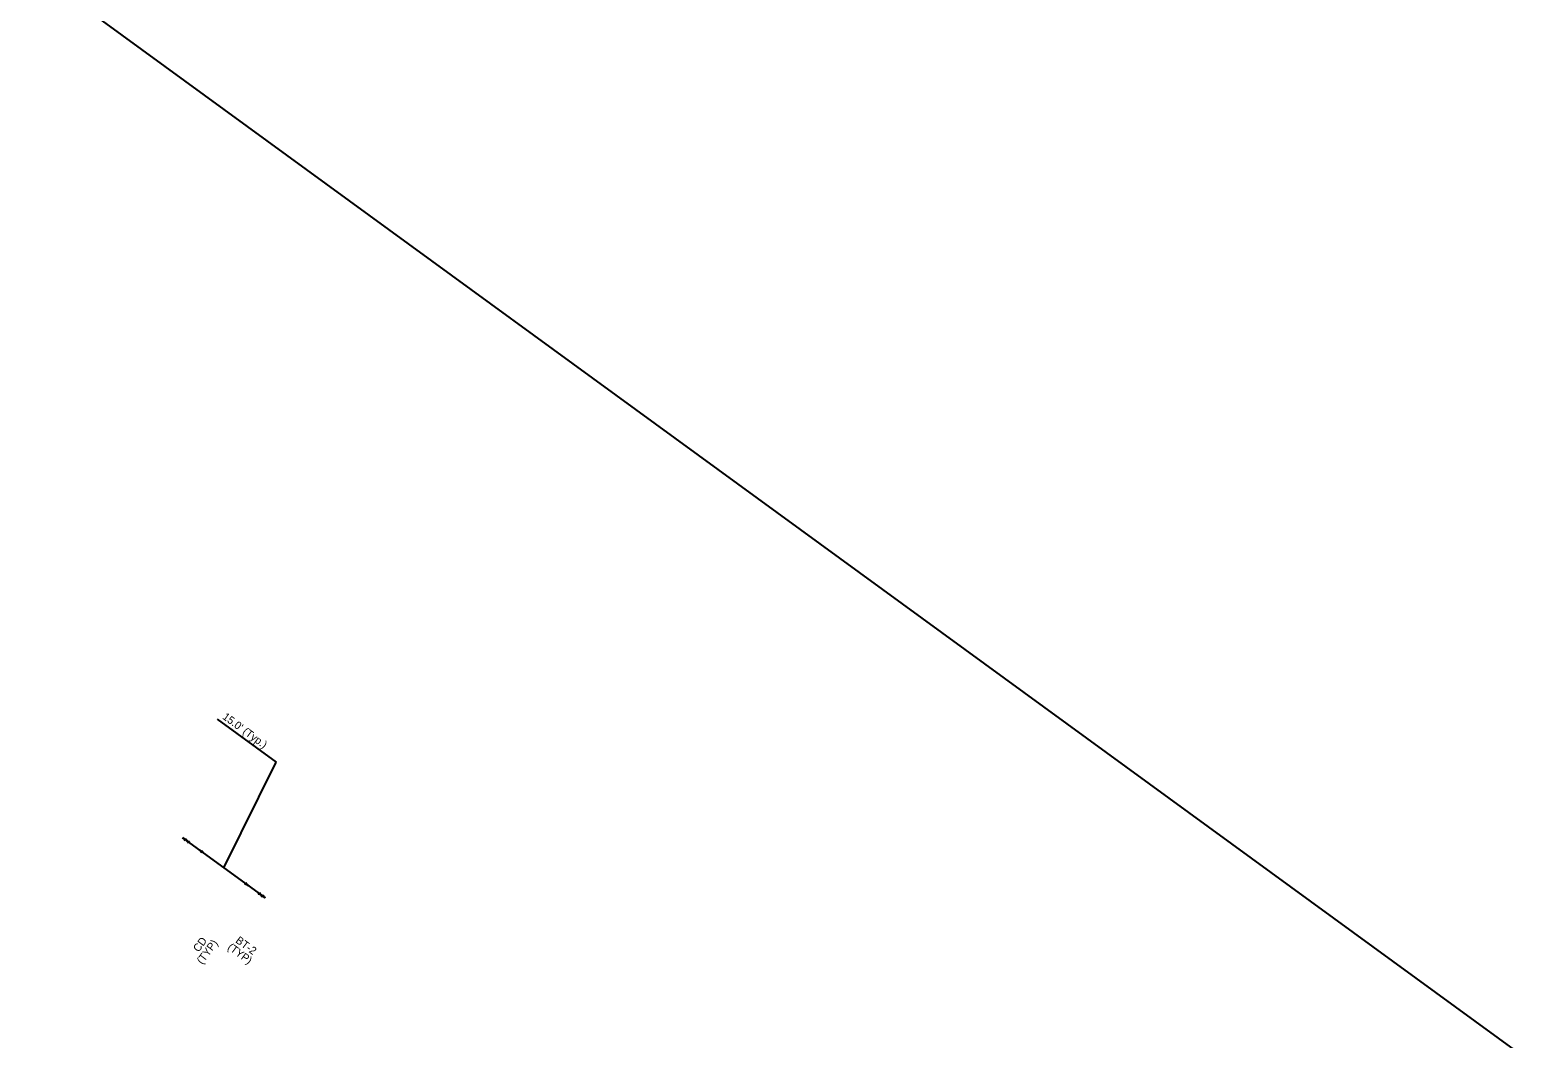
# Model space of a CAD drawing. Extents: x 15567221 to 15568484, y 8782768 to 8783889.
# Drawn here: x 15568115.4 to 15568484, y 8783249.6 to 8783496.3 of the extents above; entities that cross this region are included whole.
import ezdxf

# ---------------------------------------------------------------- set-up
doc = ezdxf.new("R2010")
doc.units = 0
for name, color, linetype in [('Drainage', 7, 'Continuous'), ('EXT_GU', 7, 'Continuous'), ('NamedBoundary', 7, 'Continuous')]:
    doc.layers.add(name, color=color, linetype=linetype)

msp = doc.modelspace()

# ---------------------------------------------------------------- linework, layer by layer
at = {"layer": 'Drainage'}
for p, q in [((15568161.18, 8783327.8), (15568175.54, 8783317.33)), ((15568162.79, 8783291.47), (15568175.54, 8783317.33)), ((15568152.69, 8783298.83), (15568172.89, 8783284.1))]:
    msp.add_line(p, q, dxfattribs=at)
at = {"layer": 'EXT_GU'}
for p, q in [((15568152.69, 8783298.83), (15568153.08, 8783298.55)), ((15568152.69, 8783298.83), (15568153.47, 8783298.27)), ((15568153.47, 8783298.27), (15568153.86, 8783297.98)), ((15568153.47, 8783298.27), (15568154.24, 8783297.7)), ((15568156.73, 8783295.89), (15568157.12, 8783295.6)), ((15568156.73, 8783295.89), (15568157.51, 8783295.32)), ((15568168.85, 8783287.05), (15568168.07, 8783287.62)), ((15568168.85, 8783287.05), (15568168.46, 8783287.34)), ((15568172.11, 8783284.67), (15568171.34, 8783285.24)), ((15568172.11, 8783284.67), (15568171.72, 8783284.96)), ((15568172.89, 8783284.1), (15568172.11, 8783284.67)), ((15568172.89, 8783284.1), (15568172.5, 8783284.39))]:
    msp.add_line(p, q, dxfattribs=at)
for centre, radius, start, end in [((15568153.94, 8783300.55), 2.12, 233.9055, 261.978), ((15568151.44, 8783297.12), 2.12, 25.833, 53.9055), ((15568154.13, 8783297.78), 0.821, 126.1722, 161.6389), ((15568154.72, 8783299.98), 2.12, 233.9055, 261.978), ((15568152.21, 8783296.55), 2.12, 25.833, 53.9055), ((15568154.91, 8783297.22), 0.821, 126.1722, 161.6389), ((15568157.98, 8783297.6), 2.12, 233.9055, 261.978), ((15568155.48, 8783294.17), 2.12, 25.833, 53.9055), ((15568158.17, 8783294.84), 0.821, 126.1722, 161.6389), ((15568167.41, 8783288.1), 0.821, 306.1722, 341.6389), ((15568167.6, 8783285.33), 2.12, 53.9055, 81.978), ((15568170.1, 8783288.77), 2.12, 205.833, 233.9055), ((15568170.67, 8783285.72), 0.821, 306.1722, 341.6389), ((15568170.86, 8783282.95), 2.12, 53.9055, 81.978), ((15568173.37, 8783286.39), 2.12, 205.833, 233.9055), ((15568171.45, 8783285.15), 0.821, 306.1722, 341.6389), ((15568171.64, 8783282.39), 2.12, 53.9055, 81.978), ((15568174.14, 8783285.82), 2.12, 205.833, 233.9055)]:
    msp.add_arc(centre, radius, start, end, dxfattribs=at)
at = {"layer": 'NamedBoundary'}
msp.add_lwpolyline([(15568248.32, 8782919.55), (15568483.96, 8783242.77), (15567982.56, 8783608.32), (15567746.92, 8783285.1)], close=True, dxfattribs=at)

# ---------------------------------------------------------------- texts
at = {"layer": 'Drainage'}
for s, height, rotation, p in [("15.0' (Typ.)", 1.8898, 323.7364, (15568162.28, 8783328.04)), ('CD', 1.89, 53.4236, (15568156.61, 8783270.71)), ('(TYP)', 1.89, 53.4236, (15568157.5, 8783267.73)), ('(TYP)', 1.89, 323.584, (15568163.52, 8783271.7)), ('BT-2', 1.89, 323.584, (15568165.48, 8783273.35))]:
    msp.add_text(s, height=height, rotation=rotation, dxfattribs=at).set_placement(p)

doc.saveas('drawing.dxf')
